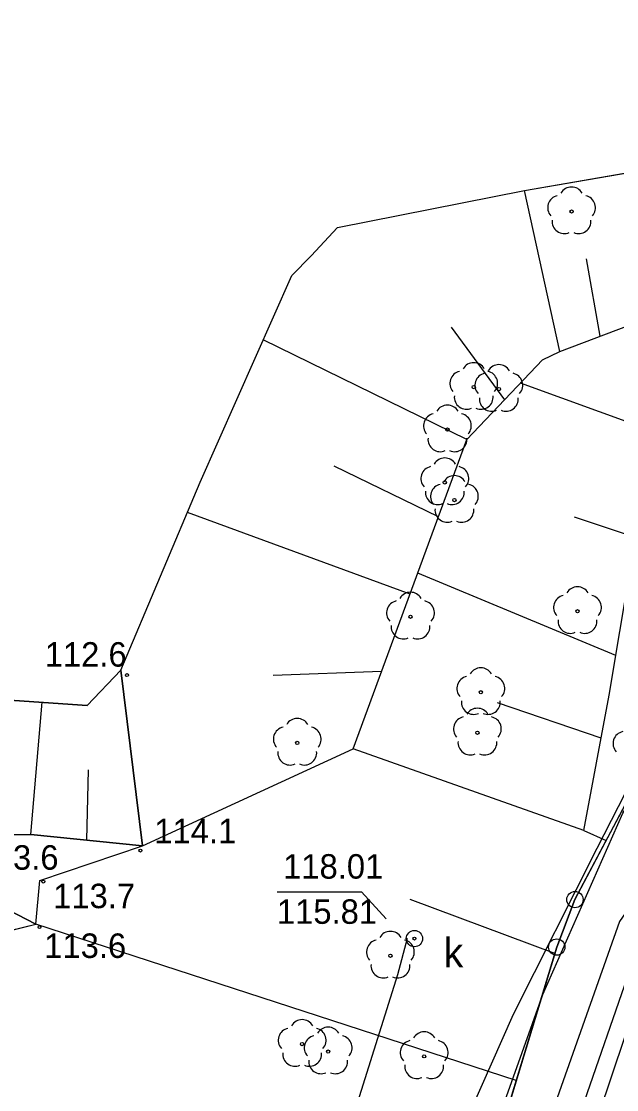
# Model space of a CAD drawing. Extents: x 6434771 to 6436222, y 5663454 to 5664782.
# Drawn here: x 6434857.69 to 6434875.92, y 5664042.15 to 5664074.89 of the extents above; entities that cross this region are included whole.
import ezdxf

# ---------------------------------------------------------------- set-up
doc = ezdxf.new("R2010")
doc.units = 0
for name, color, linetype in [('Warstwa 1', 7, 'Continuous'), ('Warstwa 10', 7, 'Continuous'), ('Warstwa 11', 7, 'Continuous'), ('Warstwa 12', 7, 'Continuous'), ('Warstwa 13', 7, 'Continuous'), ('Warstwa 14', 7, 'Continuous'), ('Warstwa 2', 7, 'Continuous'), ('Warstwa 20', 7, 'Continuous'), ('Warstwa 21', 7, 'Continuous'), ('Warstwa 4', 7, 'Continuous'), ('Warstwa 5', 7, 'Continuous'), ('Warstwa 6', 7, 'Continuous'), ('Warstwa 7', 7, 'Continuous'), ('Warstwa 8', 7, 'Continuous'), ('Warstwa 9', 7, 'Continuous')]:
    doc.layers.add(name, color=color, linetype=linetype)

msp = doc.modelspace()

# ---------------------------------------------------------------- linework, layer by layer
at = {"layer": 'Warstwa 1'}
for p, q in [((6434874.644, 5664047.97), (6434876.742, 5664051.944)), ((6434874.644, 5664047.97), (6434876.742, 5664051.944)), ((6434874.086, 5664046.517), (6434874.644, 5664047.97)), ((6434874.086, 5664046.517), (6434874.644, 5664047.97)), ((6434867.472, 5664024.707), (6434874.086, 5664046.517)), ((6434867.472, 5664024.707), (6434874.086, 5664046.517))]:
    msp.add_line(p, q, dxfattribs=at)
at = {"layer": 'Warstwa 10'}
for p, q in [((6434873.102, 5664069.709), (6434878.457, 5664070.631)), ((6434867.374, 5664068.572), (6434873.102, 5664069.709)), ((6434874.18, 5664064.768), (6434873.102, 5664069.709)), ((6434866.565, 5664067.707), (6434867.374, 5664068.572)), ((6434865.974, 5664067.104), (6434866.565, 5664067.707)), ((6434875.417, 5664065.237), (6434874.997, 5664067.613)), ((6434863.166, 5664060.762), (6434865.974, 5664067.104)), ((6434874.18, 5664064.768), (6434876.655, 5664065.706)), ((6434874.18, 5664064.768), (6434876.655, 5664065.706)), ((6434872.491, 5664063.293), (6434870.867, 5664065.515)), ((6434871.332, 5664062.075), (6434865.101, 5664065.132)), ((6434873.649, 5664064.511), (6434874.18, 5664064.768)), ((6434873.649, 5664064.511), (6434874.18, 5664064.768)), ((6434871.332, 5664062.075), (6434873.649, 5664064.511)), ((6434871.332, 5664062.075), (6434873.649, 5664064.511)), ((6434877.037, 5664062.32), (6434872.971, 5664063.798)), ((6434875.688, 5664054.24), (6434877.037, 5664062.32)), ((6434867.852, 5664052.589), (6434871.332, 5664062.075)), ((6434867.852, 5664052.589), (6434871.332, 5664062.075)), ((6434870.462, 5664059.703), (6434867.271, 5664061.252)), ((6434860.738, 5664054.998), (6434863.166, 5664060.762)), ((6434869.593, 5664057.332), (6434862.775, 5664059.833)), ((6434876.494, 5664059.071), (6434874.63, 5664059.695)), ((6434875.891, 5664055.457), (6434869.828, 5664057.977)), ((6434860.738, 5664054.998), (6434861.403, 5664049.62)), ((6434868.722, 5664054.961), (6434865.406, 5664054.844)), ((6434874.912, 5664050.092), (6434875.688, 5664054.24)), ((6434875.441, 5664052.921), (6434872.273, 5664054.004)), ((6434861.403, 5664049.62), (6434867.852, 5664052.589)), ((6434861.403, 5664049.62), (6434867.852, 5664052.589)), ((6434874.912, 5664050.092), (6434867.852, 5664052.589)), ((6434874.912, 5664050.092), (6434875.601, 5664049.782)), ((6434874.644, 5664047.97), (6434875.601, 5664049.782)), ((6434858.26, 5664048.559), (6434861.403, 5664049.62)), ((6434858.133, 5664047.22), (6434858.26, 5664048.559)), ((6434874.025, 5664046.316), (6434869.593, 5664047.973)), ((6434874.086, 5664046.517), (6434874.644, 5664047.97)), ((6434854.964, 5664046.429), (6434858.133, 5664047.22)), ((6434872.845, 5664042.425), (6434858.133, 5664047.22)), ((6434867.472, 5664024.707), (6434874.086, 5664046.517))]:
    msp.add_line(p, q, dxfattribs=at)
msp.add_lwpolyline([(6434878.796, 5664048.89), (6434876.97, 5664046.14), (6434872.156, 5664031.828), (6434869.352, 5664023.309)], dxfattribs=at)
for centre in [(6434874.644, 5664047.97), (6434874.086, 5664046.517)]:
    msp.add_circle(centre, 0.25, dxfattribs=at)
at = {"layer": 'Warstwa 11'}
msp.add_lwpolyline([(6434851.167, 5664034.04), (6434853.244, 5664039.819), (6434854.707, 5664043.362), (6434852.082, 5664049.633), (6434852.968, 5664051.803), (6434853.919, 5664054.321), (6434859.705, 5664053.921), (6434860.738, 5664054.998), (6434863.166, 5664060.762), (6434865.974, 5664067.104), (6434866.565, 5664067.707), (6434867.374, 5664068.572), (6434873.102, 5664069.709), (6434878.457, 5664070.631), (6434879.06, 5664070.809), (6434879.426, 5664100.89), (6434877.935, 5664101.425), (6434879.465, 5664104.305), (6434880.206, 5664165.364)], dxfattribs=at)
for centre in [(6434874.539, 5664069.061), (6434871.543, 5664063.677), (6434872.313, 5664063.618), (6434870.738, 5664062.377), (6434870.658, 5664060.758), (6434870.952, 5664060.215), (6434874.721, 5664056.809), (6434869.608, 5664056.641), (6434871.761, 5664054.325), (6434871.656, 5664053.086), (6434866.141, 5664052.773), (6434868.993, 5664046.248), (6434866.29, 5664043.541), (6434867.087, 5664043.312), (6434870.026, 5664043.166)]:
    msp.add_circle(centre, 0.05, dxfattribs=at)
for centre, start, end in [((6434874.539, 5664069.436), 30.1471, 149.8529), ((6434874.182, 5664069.177), 102.1471, 221.8529), ((6434874.896, 5664069.177), 318.1471, 77.8529), ((6434874.319, 5664068.758), 174.1471, 293.8529), ((6434874.759, 5664068.758), 246.1471, 5.8529), ((6434871.543, 5664064.052), 30.1471, 149.8529), ((6434871.186, 5664063.793), 102.1471, 221.8529), ((6434871.956, 5664063.734), 102.1471, 221.8529), ((6434871.9, 5664063.793), 318.1471, 77.8529), ((6434872.313, 5664063.993), 30.1471, 149.8529), ((6434872.67, 5664063.734), 318.1471, 77.8529), ((6434871.323, 5664063.374), 174.1471, 293.8529), ((6434871.763, 5664063.374), 246.1471, 5.8529), ((6434870.738, 5664062.752), 30.1471, 149.8529), ((6434872.093, 5664063.315), 174.1471, 293.8529), ((6434872.533, 5664063.315), 246.1471, 5.8529), ((6434870.381, 5664062.493), 102.1471, 221.8529), ((6434871.095, 5664062.493), 318.1471, 77.8529), ((6434870.518, 5664062.074), 174.1471, 293.8529), ((6434870.958, 5664062.074), 246.1471, 5.8529), ((6434870.658, 5664061.133), 30.1471, 149.8529), ((6434870.301, 5664060.874), 102.1471, 221.8529), ((6434871.015, 5664060.874), 318.1471, 77.8529), ((6434870.952, 5664060.59), 30.1471, 149.8529), ((6434870.438, 5664060.455), 174.1471, 293.8529), ((6434870.595, 5664060.331), 102.1471, 221.8529), ((6434870.878, 5664060.455), 246.1471, 5.8529), ((6434871.309, 5664060.331), 318.1471, 77.8529), ((6434870.732, 5664059.912), 174.1471, 293.8529), ((6434871.172, 5664059.912), 246.1471, 5.8529), ((6434874.721, 5664057.184), 30.1471, 149.8529), ((6434869.608, 5664057.016), 30.1471, 149.8529), ((6434874.364, 5664056.925), 102.1471, 221.8529), ((6434875.078, 5664056.925), 318.1471, 77.8529), ((6434869.251, 5664056.757), 102.1471, 221.8529), ((6434869.965, 5664056.757), 318.1471, 77.8529), ((6434874.501, 5664056.506), 174.1471, 293.8529), ((6434874.941, 5664056.506), 246.1471, 5.8529), ((6434869.388, 5664056.338), 174.1471, 293.8529), ((6434869.828, 5664056.338), 246.1471, 5.8529), ((6434871.761, 5664054.7), 30.1471, 149.8529), ((6434871.404, 5664054.441), 102.1471, 221.8529), ((6434872.118, 5664054.441), 318.1471, 77.8529), ((6434871.541, 5664054.022), 174.1471, 293.8529), ((6434871.981, 5664054.022), 246.1471, 5.8529), ((6434871.656, 5664053.461), 30.1471, 149.8529), ((6434865.784, 5664052.889), 102.1471, 221.8529), ((6434866.141, 5664053.148), 30.1471, 149.8529), ((6434866.498, 5664052.889), 318.1471, 77.8529), ((6434871.299, 5664053.202), 102.1471, 221.8529), ((6434872.013, 5664053.202), 318.1471, 77.8529), ((6434876.184, 5664052.753), 102.1471, 221.8529), ((6434871.436, 5664052.783), 174.1471, 293.8529), ((6434871.876, 5664052.783), 246.1471, 5.8529), ((6434865.921, 5664052.47), 174.1471, 293.8529), ((6434866.361, 5664052.47), 246.1471, 5.8529), ((6434868.636, 5664046.364), 102.1471, 221.8529), ((6434868.993, 5664046.623), 30.1471, 149.8529), ((6434869.35, 5664046.364), 318.1471, 77.8529), ((6434868.773, 5664045.945), 174.1471, 293.8529), ((6434869.213, 5664045.945), 246.1471, 5.8529), ((6434866.29, 5664043.916), 30.1471, 149.8529), ((6434865.933, 5664043.657), 102.1471, 221.8529), ((6434866.73, 5664043.428), 102.1471, 221.8529), ((6434866.647, 5664043.657), 318.1471, 77.8529), ((6434867.087, 5664043.687), 30.1471, 149.8529), ((6434867.444, 5664043.428), 318.1471, 77.8529), ((6434870.026, 5664043.541), 30.1471, 149.8529), ((6434869.669, 5664043.282), 102.1471, 221.8529), ((6434870.383, 5664043.282), 318.1471, 77.8529), ((6434866.07, 5664043.238), 174.1471, 293.8529), ((6434866.51, 5664043.238), 246.1471, 5.8529), ((6434866.867, 5664043.009), 174.1471, 293.8529), ((6434867.307, 5664043.009), 246.1471, 5.8529), ((6434869.806, 5664042.863), 174.1471, 293.8529), ((6434870.246, 5664042.863), 246.1471, 5.8529)]:
    msp.add_arc(centre, 0.375, start, end, dxfattribs=at)
at = {"layer": 'Warstwa 12'}
for points in [[(6434864.828, 5664025.979), (6434868.129, 5664033.986), (6434872.765, 5664044.46), (6434875.32, 5664049.543), (6434876.842, 5664052.524), (6434877.517, 5664053.754), (6434878.873, 5664055.304)], [(6434864.849, 5664025.966), (6434865.093, 5664026.456), (6434869.188, 5664025.206), (6434876.877, 5664047.393), (6434878.175, 5664051.337), (6434878.837, 5664052.303)], [(6434878.826, 5664051.371), (6434876.003, 5664047.297), (6434872.792, 5664038.193), (6434868.701, 5664026.207), (6434867.961, 5664024.13)]]:
    msp.add_lwpolyline(points, dxfattribs=at)
at = {"layer": 'Warstwa 13'}
for centre in [(6434860.927, 5664054.852), (6434861.34, 5664049.473), (6434858.366, 5664048.524), (6434858.248, 5664047.128)]:
    msp.add_circle(centre, 0.045, dxfattribs=at)
at = {"layer": 'Warstwa 14'}
msp.add_lwpolyline([(6434865.524, 5664048.208), (6434868.11, 5664048.208), (6434868.858, 5664047.385)], dxfattribs=at)
msp.add_circle((6434869.729, 5664046.775), 0.045, dxfattribs=at)
at = {"layer": 'Warstwa 2'}
msp.add_lwpolyline([(6434867.191, 5664024.874), (6434872.127, 5664040.76), (6434873.659, 5664045.062), (6434876.106, 5664050.622), (6434878.207, 5664053.997), (6434878.868, 5664054.874)], dxfattribs=at)
at = {"layer": 'Warstwa 20'}
for p, q in [((6434874.18, 5664064.768), (6434876.655, 5664065.706)), ((6434873.649, 5664064.511), (6434874.18, 5664064.768)), ((6434871.332, 5664062.075), (6434873.649, 5664064.511)), ((6434875.688, 5664054.24), (6434877.037, 5664062.32)), ((6434867.852, 5664052.589), (6434871.332, 5664062.075)), ((6434874.912, 5664050.092), (6434875.688, 5664054.24)), ((6434861.403, 5664049.62), (6434867.852, 5664052.589)), ((6434874.912, 5664050.092), (6434875.601, 5664049.782)), ((6434874.644, 5664047.97), (6434875.601, 5664049.782)), ((6434874.086, 5664046.517), (6434874.644, 5664047.97)), ((6434867.472, 5664024.707), (6434874.086, 5664046.517))]:
    msp.add_line(p, q, dxfattribs=at)
msp.add_lwpolyline([(6434861.403, 5664049.62), (6434857.987, 5664049.962), (6434856.176, 5664049.954), (6434856.168, 5664049.274), (6434856.103, 5664048.035), (6434856.981, 5664047.814), (6434858.133, 5664047.22)], dxfattribs=at)
at = {"layer": 'Warstwa 21'}
for p, q in [((6434873.102, 5664069.709), (6434878.457, 5664070.631)), ((6434867.374, 5664068.572), (6434873.102, 5664069.709)), ((6434866.565, 5664067.707), (6434867.374, 5664068.572)), ((6434865.974, 5664067.104), (6434866.565, 5664067.707)), ((6434863.166, 5664060.762), (6434865.974, 5664067.104)), ((6434874.18, 5664064.768), (6434876.655, 5664065.706)), ((6434873.649, 5664064.511), (6434874.18, 5664064.768)), ((6434871.332, 5664062.075), (6434873.649, 5664064.511)), ((6434867.852, 5664052.589), (6434871.332, 5664062.075)), ((6434860.738, 5664054.998), (6434863.166, 5664060.762)), ((6434861.403, 5664049.62), (6434867.852, 5664052.589)), ((6434858.26, 5664048.559), (6434861.403, 5664049.62)), ((6434858.133, 5664047.22), (6434858.26, 5664048.559)), ((6434854.964, 5664046.429), (6434858.133, 5664047.22))]:
    msp.add_line(p, q, dxfattribs=at)
msp.add_lwpolyline([(6434854.707, 5664043.362), (6434852.082, 5664049.633), (6434852.968, 5664051.803), (6434853.919, 5664054.321), (6434859.705, 5664053.921), (6434860.738, 5664054.998)], dxfattribs=at)
at = {"layer": 'Warstwa 4'}
msp.add_circle((6434869.729, 5664046.775), 0.25, dxfattribs=at)
at = {"layer": 'Warstwa 6'}
for points in [[(6434849.064, 5664112.586), (6434898.465, 5664094.951), (6434890.58, 5664073.12), (6434890.292, 5664072.48), (6434890.073, 5664072.573), (6434886.997, 5664065.49), (6434876.742, 5664051.944), (6434874.644, 5664047.97), (6434874.086, 5664046.517), (6434867.472, 5664024.707), (6434867.386, 5664024.469)], [(6434872.329, 5664021.552), (6434876.932, 5664037.822), (6434878.714, 5664042.95), (6434879.824, 5664045.447), (6434885.357, 5664054.75), (6434896.533, 5664070.874), (6434890.292, 5664072.48), (6434890.073, 5664072.573), (6434886.997, 5664065.49), (6434876.742, 5664051.944), (6434874.644, 5664047.97), (6434874.086, 5664046.517), (6434867.472, 5664024.707), (6434867.386, 5664024.469)]]:
    msp.add_lwpolyline(points, dxfattribs=at)
msp.add_circle((6434869.729, 5664046.775), 0.045, dxfattribs=at)
at = {"layer": 'Warstwa 7'}
msp.add_lwpolyline([(6434863.379, 5664026.834), (6434866.378, 5664036.633), (6434869.221, 5664045.679), (6434869.512, 5664046.79)], dxfattribs=at)
at = {"layer": 'Warstwa 8'}
for p, q in [((6434873.659, 5664045.062), (6434876.106, 5664050.622)), ((6434867.491, 5664024.77), (6434873.563, 5664044.793)), ((6434873.563, 5664044.793), (6434873.659, 5664045.062))]:
    msp.add_line(p, q, dxfattribs=at)
at = {"layer": 'Warstwa 9'}
for p, q in [((6434861.403, 5664049.62), (6434860.738, 5664054.998)), ((6434857.987, 5664049.962), (6434858.329, 5664054.017)), ((6434859.695, 5664049.791), (6434859.754, 5664051.953)), ((6434858.1, 5664047.237), (6434858.092, 5664047.223))]:
    msp.add_line(p, q, dxfattribs=at)
msp.add_lwpolyline([(6434860.738, 5664054.998), (6434859.705, 5664053.921), (6434853.919, 5664054.321), (6434852.968, 5664051.803), (6434852.082, 5664049.633), (6434854.707, 5664043.362), (6434854.964, 5664046.429), (6434858.133, 5664047.22), (6434856.981, 5664047.814), (6434856.103, 5664048.035), (6434856.168, 5664049.274), (6434856.176, 5664049.954), (6434857.987, 5664049.962), (6434861.403, 5664049.62)], close=True, dxfattribs=at)

# ---------------------------------------------------------------- texts
at = {"layer": 'Warstwa 13'}
for s, p in [('112.6', (6434858.408, 5664055.111)), ('114.1', (6434861.763, 5664049.698)), ('113.6', (6434856.322, 5664048.888)), ('113.7', (6434858.666, 5664047.708)), ('113.6', (6434858.393, 5664046.183))]:
    msp.add_text(s, height=0.75, dxfattribs=at).set_placement(p)
at = {"layer": 'Warstwa 14'}
msp.add_text('115.81', height=0.75, dxfattribs=at).set_placement((6434865.517, 5664047.228))
at = {"layer": 'Warstwa 5'}
msp.add_text('k', height=0.9, dxfattribs=at).set_placement((6434870.62, 5664045.898))
at = {"layer": 'Warstwa 6'}
msp.add_text('118.01', height=0.75, dxfattribs=at).set_placement((6434865.707, 5664048.613))

doc.saveas('drawing.dxf')
